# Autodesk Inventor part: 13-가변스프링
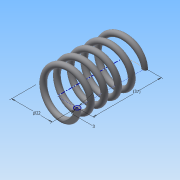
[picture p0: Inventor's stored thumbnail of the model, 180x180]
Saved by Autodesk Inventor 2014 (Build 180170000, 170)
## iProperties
Created: 2015-09
Part Number: 13-가변스프링
Material: 강철, 탄소
Document SubType Name: Modeling
Designer: study
Density: 7.87 g/cm^3
Appearance: 반연마
Mass: 18.7691 g
Surface Area: 32.4279 cm^2
Volume: 2.3849 cm^3
Author: study
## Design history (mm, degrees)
sketch "스케치1"
  geometry: L1 (0, 0)-(11, 0); L2 (11, 0)-(11, 28.893); L3 (11, 28.893)-(0, 28.893); L4 (0, 28.893)-(0, 0); C1 r 1.5 at (11, 0)
  constraints: 8 end point, 2 parallel, 1 centre point, 1 coincident, 1 horizontal, 1 perpendicular
  dimensions: "d0" = 3 diameter of C1; "d1" = 22 diameter of L2 L4; "d2" = 28.89259 distance of L1.end L2.end (derived)
feature "코일1" pitch "d3" = 10; turns "d5" = 5; dims "d4" = 28.89259 (= d2), "d6" = 0, angle "d7" = 90 deg, angle "d8" = 90 deg, "d9" = 0, "d10" = 0
node "작업 평면1"
sketch "스케치2"
  geometry: L1 (-12.5, 0)-(-9.5, 0) reference; L2 (-12.5, 0)-(-9.5, 0) reference; 1 further point
  constraints: 2 horizontal alignment
extrude "돌출1" cut sketch "스케치2" stored distance "d12" = 10; taper "d13" = 0 deg
node "작업 평면2"
sketch "스케치3"
  geometry: L1 (-9.5, 0)-(-12.5, 0) reference; 1 further point
  constraints: 1 horizontal alignment
extrude "돌출2" cut sketch "스케치3" stored distance "d15" = 10; taper "d16" = 0 deg
node "솔리드1"
node "절단 모서리 투영1"
node "절단 모서리 투영2"
node "절단 모서리 투영3"
other parameters: "d11" = 0, "d14" = 28.89259 (= d2)
